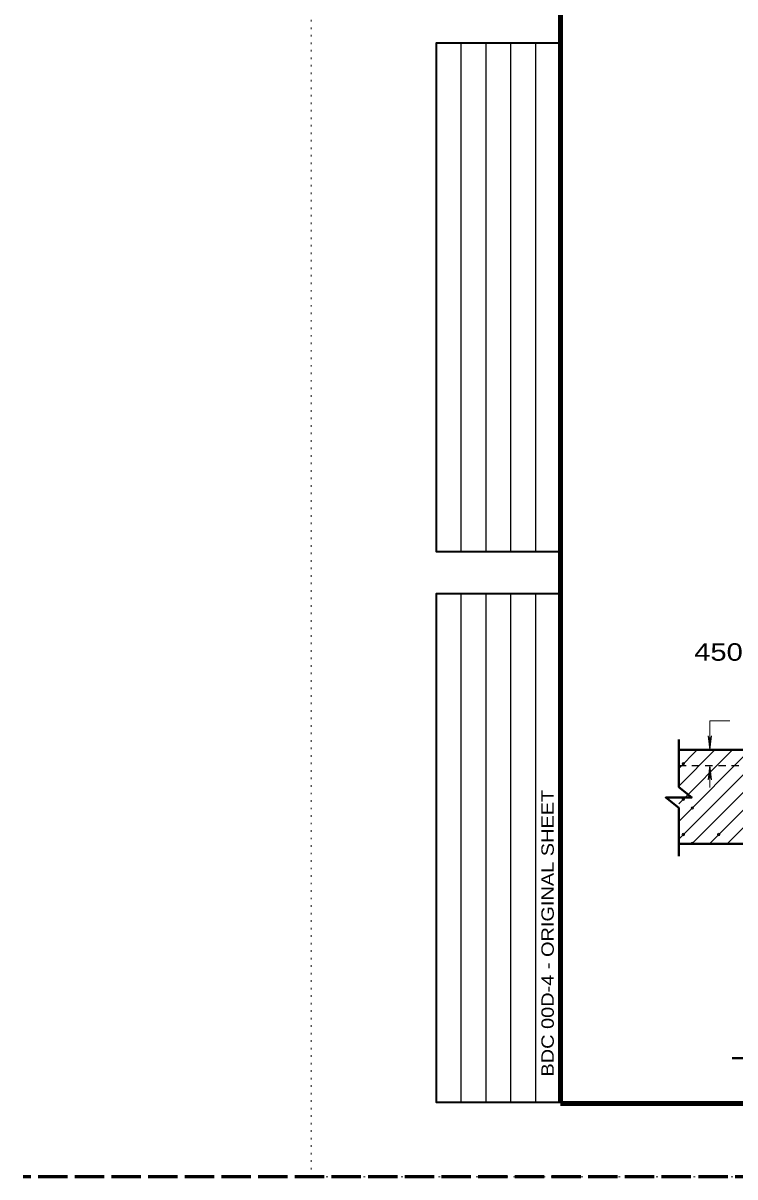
# Model space of a CAD drawing. Extents: x 312583 to 312854, y 144419 to 144597.
# Drawn here: x 312583.5 to 312627.2, y 144418.6 to 144489.3 of the extents above; entities that cross this region are included whole.
import ezdxf
from ezdxf.enums import TextEntityAlignment as Align

# ---------------------------------------------------------------- set-up
doc = ezdxf.new("R2010")
doc.units = 0
doc.header["$LTSCALE"] = 0.3
doc.header["$PDMODE"] = 32
doc.header["$PDSIZE"] = 0.15
for name, pattern in [('DOTTED', [1.5, 0.3, -1.2]), ('LONG_DASHED', [7.5, 6, -1.5]), ('SHORT_DASHED', [2.7, 1.5, -1.2])]:
    doc.linetypes.add(name, pattern=pattern)
doc.layers.add('1', color=7, linetype='Continuous', lineweight=13)

msp = doc.modelspace()

# ---------------------------------------------------------------- linework, layer by layer
at = {"layer": '1', "linetype": 'DOTTED'}
for q in [(312601.2, 144596.7846), (312853.5, 144418.5846)]:
    msp.add_line((312601.2, 144418.5846), q, dxfattribs=at)
at = {"layer": '1', "lineweight": 25}
for p, q in [((312610.4087, 144456.901), (312610.4087, 144488.1192)), ((312611.9315, 144456.901), (312611.9315, 144488.1192)), ((312613.4543, 144456.901), (312613.4543, 144488.1192)), ((312614.9772, 144456.901), (312614.9772, 144488.1192)), ((312610.4087, 144423.1446), (312610.4087, 144454.3629)), ((312611.9315, 144423.1446), (312611.9315, 144454.3629)), ((312613.4543, 144423.1446), (312613.4543, 144454.3629)), ((312614.9772, 144423.1446), (312614.9772, 144454.3629))]:
    msp.add_line(p, q, dxfattribs=at)
at = {"layer": '1'}
for p, q in [((312625.657, 144444.7607), (312625.657, 144446.5471)), ((312625.657, 144446.5471), (312626.876, 144446.5471)), ((312625.5497, 144445.6271), (312625.657, 144445.3511)), ((312625.657, 144444.7607), (312625.5497, 144445.6271)), ((312625.7644, 144445.6271), (312625.657, 144445.3511)), ((312625.657, 144444.7607), (312625.7644, 144445.6271)), ((312623.748, 144439.2944), (312629.2144, 144444.7607)), ((312623.748, 144440.3754), (312628.1334, 144444.7607)), ((312623.748, 144441.4641), (312627.0524, 144444.7607)), ((312623.748, 144442.5451), (312625.9637, 144444.7607)), ((312623.748, 144443.6337), (312624.8827, 144444.7607)), ((312623.748, 144444.7147), (312623.794, 144444.7607)), ((312624.553, 144439.0107), (312630.2954, 144444.7607)), ((312625.634, 144439.0107), (312631.384, 144444.7607)), ((312626.715, 144439.0107), (312632.465, 144444.7607)), ((312625.657, 144443.8024), (312625.5497, 144442.9361)), ((312625.657, 144442.4684), (312625.657, 144443.8024)), ((312625.657, 144443.8024), (312625.7644, 144442.9361)), ((312625.5497, 144442.9361), (312625.657, 144443.2121)), ((312625.7644, 144442.9361), (312625.657, 144443.2121))]:
    msp.add_line(p, q, dxfattribs=at)
at = {"layer": '1', "lineweight": 40}
for p, q in [((312623.748, 144445.3971), (312623.748, 144442.4914)), ((312623.748, 144444.7607), (312645.0384, 144444.7607)), ((312623.748, 144441.2111), (312623.748, 144438.2594)), ((312623.748, 144439.0107), (312630.0194, 144439.0107)), ((312627.0227, 144425.8701), (312641.8341, 144425.8701))]:
    msp.add_line(p, q, dxfattribs=at)
at = {"layer": '1', "linetype": 'SHORT_DASHED', "lineweight": 25}
msp.add_line((312623.748, 144443.8024), (312645.0384, 144443.8024), dxfattribs=at)
at = {"layer": '1', "lineweight": 158}
msp.add_line((312616.5, 144423.0846), (312849, 144423.0846), dxfattribs=at)
at = {"layer": '1', "linetype": 'LONG_DASHED', "lineweight": 60}
msp.add_line((312851.75, 144418.5846), (312583.526, 144418.5846), dxfattribs=at)
at = {"layer": '1', "lineweight": 158}
msp.add_lwpolyline([(312616.5, 144423.1446), (312616.5, 144585.0846), (312849, 144585.0846)], dxfattribs=at)
at = {"layer": '1', "lineweight": 35}
for points in [[(312616.5, 144456.901), (312608.8858, 144456.901), (312608.8858, 144488.1192), (312616.5, 144488.1192)], [(312616.5, 144423.1446), (312608.8858, 144423.1446), (312608.8858, 144454.3629), (312616.5, 144454.3629)]]:
    msp.add_lwpolyline(points, dxfattribs=at)
at = {"layer": '1', "lineweight": 40}
msp.add_lwpolyline([(312623.748, 144441.2111), (312622.9507, 144441.8474), (312624.5454, 144441.8474), (312623.748, 144442.4914)], dxfattribs=at)
at = {"layer": '1'}
for p in [(312624.0317, 144443.9174), (312624.0317, 144441.7477), (312624.576, 144441.2034), (312624.0317, 144439.5781), (312624.576, 144439.0414), (312626.2014, 144439.5781)]:
    msp.add_point(p, dxfattribs=at)

# ---------------------------------------------------------------- texts
at = {"layer": '1', "width": 1.25}
msp.add_text('450 BY 900 MM SHOWN.  250 BY 900 MM SIMILAR EXCEPT AS NOTED', height=1.07, dxfattribs=at).set_placement((312654.4133, 144450.2344), align=Align.CENTER)
at = {"layer": '1', "width": 1.2}
msp.add_text('BDC 00D-4 - ORIGINAL SHEET', height=0.7614, rotation=90, dxfattribs=at).set_placement((312616.0832, 144424.7374))

doc.saveas('drawing.dxf')
